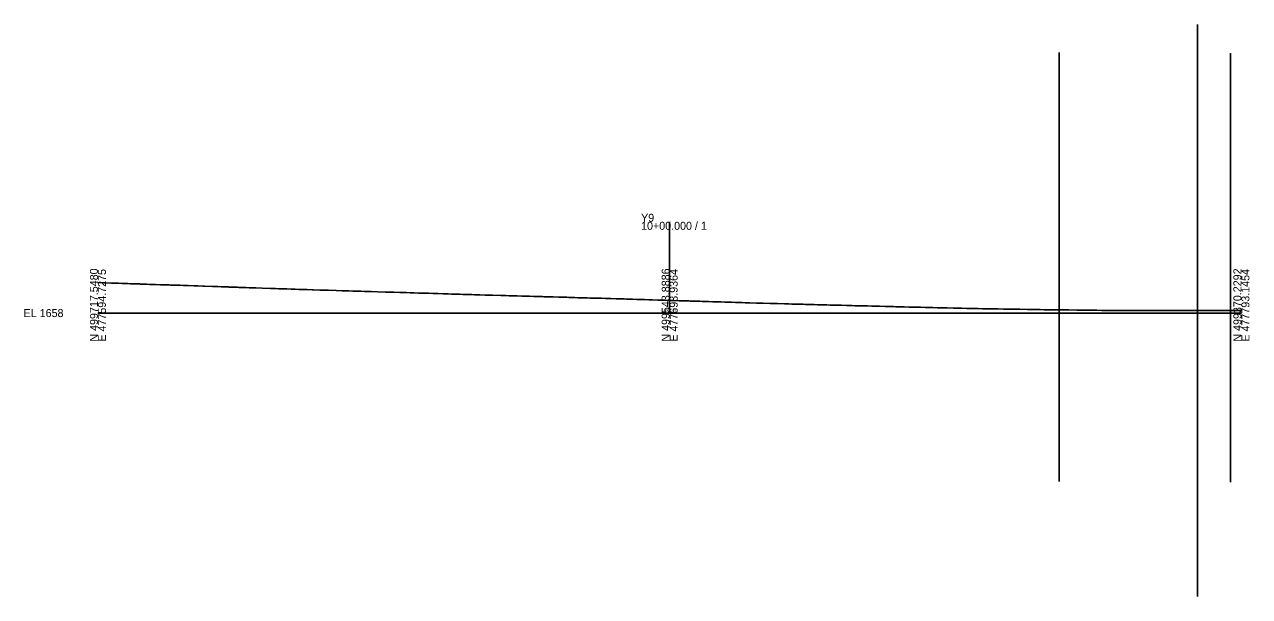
# Model space of a CAD drawing. Extents: x -26 to 403, y -99 to 4540.
# Drawn here: x -25.7 to 402.8, y -99.1 to 100.9 of the extents above; entities that cross this region are included whole.
import ezdxf

# ---------------------------------------------------------------- set-up
doc = ezdxf.new("R2010")
doc.units = 0
for name, color, linetype in [('Exist Cross Section Cell', 7, 'Continuous'), ('Exist XS Center Line Elevation Label', 7, 'Continuous'), ('Exist XS Ground Line', 7, 'Continuous'), ('Scratch_Level_1', 7, 'Continuous'), ('Scratch_Level_2', 7, 'Continuous'), ('Scratch_Level_5', 7, 'Continuous'), ('Scratch_Level_6', 7, 'Continuous')]:
    doc.layers.add(name, color=color, linetype=linetype)

msp = doc.modelspace()

# ---------------------------------------------------------------- linework, layer by layer
at = {"layer": 'Exist Cross Section Cell'}
for p, q in [((200, 0), (200, 31.91)), ((0, 0), (200, 0)), ((200, 0), (400, 0))]:
    msp.add_line(p, q, dxfattribs=at)
at = {"layer": 'Exist XS Ground Line'}
msp.add_lwpolyline([(0, 10.64), (1.9, 10.57), (2.73, 10.55), (4.74, 10.48), (5.16, 10.47), (5.67, 10.45), (7.17, 10.4), (8.47, 10.36), (9.79, 10.32), (10.46, 10.29), (11.37, 10.26), (12.66, 10.22), (14.49, 10.16), (14.85, 10.15), (16.56, 10.09), (17.13, 10.07), (18.14, 10.04), (20.08, 9.97), (21.93, 9.91), (22.9, 9.88), (23.62, 9.86), (24.96, 9.81), (25.37, 9.8), (25.79, 9.79), (26.9, 9.75), (28.65, 9.7), (29.97, 9.65), (31.53, 9.6), (33.59, 9.53), (34.39, 9.5), (34.99, 9.48), (36.68, 9.42), (37.29, 9.4), (40.13, 9.3), (41.96, 9.24), (43.07, 9.21), (43.82, 9.18), (45.09, 9.13), (45.5, 9.12), (45.91, 9.1), (47.45, 9.06), (48.83, 9.01), (49.33, 8.99), (50.16, 8.96), (51.71, 8.91), (52.93, 8.87), (54.8, 8.8), (55.21, 8.79), (57.45, 8.72), (60.32, 8.61), (62.14, 8.56), (63.19, 8.52), (65.24, 8.45), (66.07, 8.43), (67.63, 8.38), (68.97, 8.34), (70.27, 8.29), (71.25, 8.26), (71.82, 8.24), (73.12, 8.21), (74.98, 8.14), (75.36, 8.13), (77.6, 8.06), (78.59, 8.03), (80.6, 7.96), (83.35, 7.87), (85.4, 7.8), (85.92, 7.79), (86.23, 7.78), (87.79, 7.74), (89.14, 7.69), (90.45, 7.65), (91.98, 7.61), (93.26, 7.58), (95.12, 7.51), (95.53, 7.5), (97.76, 7.43), (100.63, 7.34), (102.46, 7.3), (103.52, 7.26), (105.56, 7.2), (106.37, 7.17), (107.92, 7.14), (109.28, 7.09), (109.78, 7.08), (110.66, 7.05), (112.16, 7), (114.18, 6.94), (115.25, 6.91), (115.66, 6.9), (117.1, 6.86), (117.93, 6.83), (118.95, 6.8), (120.78, 6.74), (122.57, 6.7), (123.66, 6.66), (124.42, 6.64), (125.76, 6.59), (126.56, 6.57), (127.6, 6.54), (129.41, 6.49), (130.77, 6.45), (131.74, 6.42), (132.29, 6.4), (133.58, 6.37), (135.43, 6.31), (135.84, 6.29), (137.27, 6.26), (138.07, 6.23), (140.92, 6.15), (142.74, 6.11), (143.82, 6.07), (144.58, 6.05), (145.91, 6.01), (146.7, 5.99), (148.26, 5.95), (149.6, 5.91), (150.94, 5.87), (152.45, 5.83), (153.73, 5.8), (155.56, 5.74), (155.98, 5.72), (157.4, 5.68), (158.22, 5.66), (159.24, 5.64), (161.1, 5.58), (162.91, 5.53), (163.99, 5.5), (164.75, 5.48), (166.06, 5.44), (166.86, 5.41), (167.93, 5.38), (169.73, 5.34), (170.22, 5.32), (171.09, 5.29), (172.21, 5.26), (172.61, 5.25), (173.89, 5.22), (175.72, 5.16), (176.14, 5.15), (177.61, 5.11), (178.37, 5.09), (179.39, 5.06), (181.26, 5), (183.25, 4.95), (184.14, 4.92), (184.9, 4.9), (186.23, 4.86), (186.63, 4.84), (187.02, 4.83), (188.57, 4.78), (189.89, 4.75), (191.25, 4.7), (192.77, 4.65), (194.05, 4.61), (195.88, 4.56), (196.28, 4.54), (197.97, 4.48), (198.53, 4.47), (199.55, 4.44), (200, 4.43), (201.42, 4.38), (203.28, 4.32), (204.29, 4.29), (205.04, 4.27), (206.37, 4.23), (206.67, 4.22), (207.17, 4.2), (208.49, 4.15), (210.05, 4.11), (210.54, 4.1), (211.41, 4.07), (212.62, 4.03), (213.61, 4), (215.06, 3.95), (216.04, 3.93), (216.45, 3.92), (217.92, 3.87), (219.3, 3.83), (220.24, 3.79), (221.6, 3.76), (223.06, 3.71), (224.77, 3.66), (225.34, 3.64), (226.38, 3.61), (227.39, 3.58), (228.05, 3.56), (230.33, 3.5), (231.02, 3.48), (232.71, 3.44), (235.19, 3.36), (237.1, 3.31), (237.74, 3.3), (240.12, 3.23), (241.72, 3.19), (242.72, 3.16), (243.23, 3.15), (245.16, 3.1), (246.67, 3.06), (247.48, 3.03), (247.86, 3.03), (249.77, 2.98), (250.59, 2.96), (251.71, 2.92), (252.68, 2.9), (253.35, 2.88), (254.95, 2.84), (256.1, 2.81), (256.74, 2.79), (258.18, 2.75), (259, 2.73), (260.07, 2.7), (261.89, 2.65), (263.68, 2.61), (264.76, 2.58), (265.33, 2.57), (266.82, 2.53), (267.35, 2.52), (267.65, 2.51), (269.18, 2.47), (270.76, 2.43), (271.86, 2.4), (273.4, 2.36), (275.44, 2.31), (276.58, 2.28), (276.89, 2.28), (278.32, 2.24), (279.15, 2.22), (280.16, 2.19), (282.03, 2.15), (283.83, 2.11), (284.92, 2.08), (285.66, 2.06), (286.96, 2.03), (287.49, 2.01), (287.8, 2.01), (289.33, 1.97), (290.68, 1.94), (291.17, 1.93), (292.01, 1.91), (293.57, 1.87), (294.83, 1.84), (296.44, 1.8), (297.03, 1.79), (299.3, 1.74), (300.31, 1.72), (302.19, 1.67), (303.98, 1.64), (305.07, 1.61), (305.82, 1.6), (307.13, 1.57), (307.66, 1.56), (307.97, 1.56), (309.49, 1.53), (310.84, 1.5), (312.17, 1.48), (313.7, 1.45), (314.97, 1.43), (316.8, 1.4), (317.18, 1.39), (318.64, 1.36), (319.47, 1.35), (320.49, 1.34), (322.52, 1.31), (325.22, 1.27), (325.96, 1.25), (327.27, 1.24), (327.81, 1.23), (328.12, 1.22), (329.65, 1.2), (331, 1.18), (332.32, 1.16), (333.85, 1.14), (335.12, 1.12), (336.97, 1.1), (337.36, 1.09), (338.81, 1.08), (339.64, 1.07), (342.49, 1.03), (344.29, 1.02), (345.39, 1), (346.13, 1), (347.45, 0.98), (348.29, 0.98), (349.4, 0.97), (351.13, 0.95), (351.6, 0.95), (352.45, 0.94), (353.47, 0.93), (354.04, 0.93), (356.14, 0.91), (356.89, 0.91), (357.46, 0.9), (358.95, 0.9), (359.79, 0.89), (360.82, 0.89), (362.83, 0.87), (365.54, 0.87), (366.29, 0.87), (367.6, 0.87), (368.15, 0.87), (368.62, 0.87), (370.32, 0.87), (371.29, 0.87), (371.78, 0.87), (372.65, 0.87), (373.46, 0.87), (374.29, 0.87), (375.34, 0.87), (377.29, 0.87), (377.68, 0.87), (378.33, 0.88), (379.79, 0.88), (380.27, 0.88), (382.39, 0.89), (382.73, 0.89), (384.67, 0.89), (385.01, 0.89), (387.11, 0.9), (387.67, 0.9), (388.48, 0.9), (389.65, 0.9), (390.96, 0.9), (392.02, 0.91), (392.66, 0.91), (393.6, 0.91), (395.52, 0.92), (396.31, 0.92), (397.37, 0.92), (398.19, 0.93), (400, 0.94)], dxfattribs=at)
at = {"layer": 'Scratch_Level_1'}
msp.add_line((384.67, 100.89), (384.67, -99.11), dxfattribs=at)
at = {"layer": 'Scratch_Level_2'}
msp.add_line((396.25, 50.92), (396.25, -49.08), dxfattribs=at)
at = {"layer": 'Scratch_Level_5'}
msp.add_line((396.25, 90.92), (396.25, -59.08), dxfattribs=at)
at = {"layer": 'Scratch_Level_6'}
for p, q in [((336.31, 91.1), (336.31, -58.9)), ((396.25, 90.92), (396.25, -59.08))]:
    msp.add_line(p, q, dxfattribs=at)

# ---------------------------------------------------------------- texts
at = {"layer": 'Exist Cross Section Cell'}
for s, p in [('Y9', (190, 31.91)), ('10+00.000 / 1', (190, 29.11)), ('EL 1658', (-26, -1.4))]:
    msp.add_text(s, height=2.8, dxfattribs=at).set_placement(p)
for s, p in [('N 499717.5480', (0, -10)), ('E 477594.7275', (2.8, -10)), ('N 499543.8886', (200, -10)), ('E 477693.9364', (202.8, -10)), ('N 499370.2292', (400, -10)), ('E 477793.1454', (402.8, -10))]:
    msp.add_text(s, height=2.8, rotation=90, dxfattribs=at).set_placement(p)
at = {"layer": 'Exist XS Center Line Elevation Label'}
msp.add_text('1662.43', height=0.9, dxfattribs=at).set_placement((197.86, 0.53))

doc.saveas('drawing.dxf')
